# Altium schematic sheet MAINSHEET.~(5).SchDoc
size 594 x 420 mm; Scale: 1:1; Разраб.: Иванов; Обозначение документа: АБВГ.123456.001 Э3; Пров.: Петров; Утв.: Сидоров; Наименование организации: ОАО "Концерн "МПО-Гидроприбор"; Перв. применение: АБВГ.123456.000; Наименование изделия 1: Плата; Наименование изделия 2: Схема электрическая; Наименование изделия 3: принципиальная; Нач. отд.: Нач. отд.; Фамилия нач. отд.: Сидоров
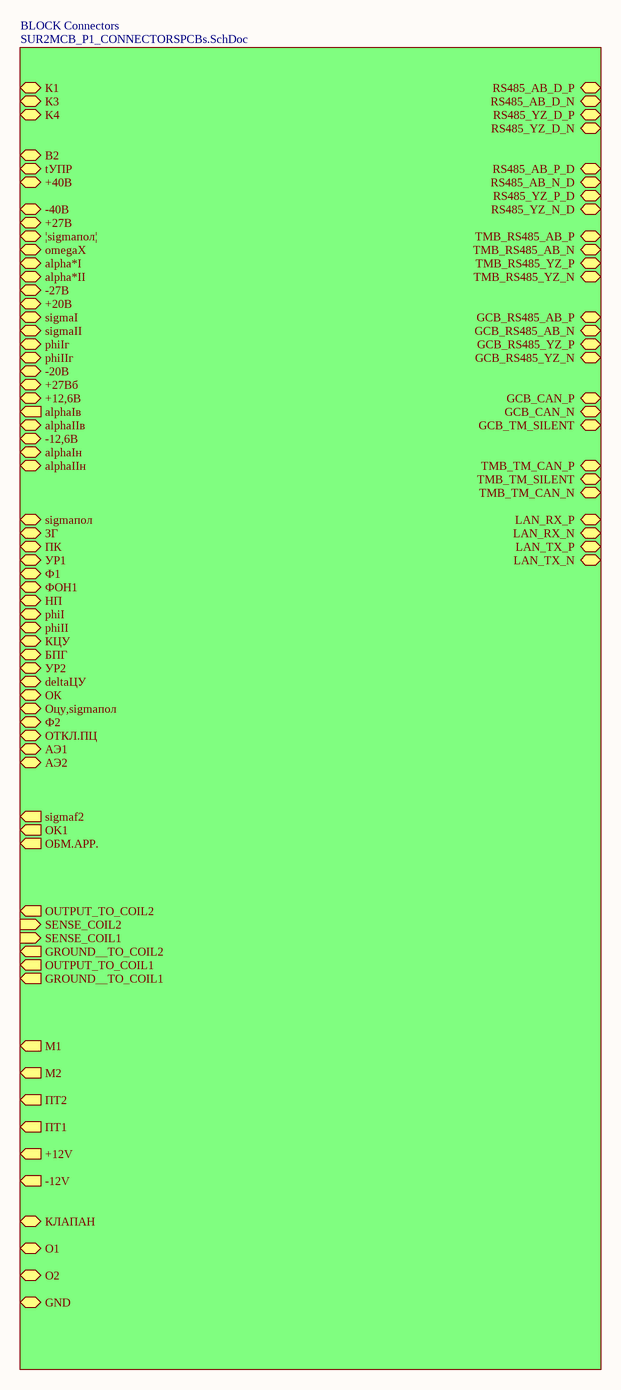
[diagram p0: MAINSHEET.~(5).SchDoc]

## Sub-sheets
BLOCK Connectors = SUR2MCB_P1_CONNECTORSPCBs.SchDoc: tУПР (bidir), B2 (bidir), K4 (bidir), +40В (bidir), К1 (bidir), К3 (bidir), OUTPUT_TO_COIL2 (out), OUTPUT_TO_COIL1 (out), GROUND__TO_COIL1 (out), SENSE_COIL2 (in), GROUND__TO_COIL2 (out), SENSE_COIL1 (in), RS485_YZ_D_N (bidir), RS485_YZ_D_P (bidir), RS485_AB_D_N (bidir), M1 (out), RS485_AB_D_P (bidir), RS485_YZ_N_D (bidir), КЛАПАН (bidir), О1 (bidir), O2 (bidir), RS485_AB_P_D (bidir), RS485_AB_N_D (bidir), RS485_YZ_P_D (bidir), TMB_RS485_AB_N (bidir), TMB_RS485_AB_P (bidir), TMB_RS485_YZ_N (bidir), TMB_RS485_YZ_P (bidir), LAN_RX_P (bidir), LAN_RX_N (bidir), LAN_TX_P (bidir), LAN_TX_N (bidir), GCB_RS485_AB_N (bidir), GCB_RS485_YZ_N (bidir), GCB_RS485_YZ_P (bidir), GCB_RS485_AB_P (bidir), GCB_CAN_P (bidir), GCB_CAN_N (bidir), GCB_TM_SILENT (bidir), TMB_TM_CAN_P (bidir), TMB_TM_SILENT (bidir), TMB_TM_CAN_N (bidir), -40В (bidir), +27В (bidir), ¦sigmaпол¦ (bidir), omegaX (bidir), alpha*II (bidir), alpha*I (bidir), -27В (bidir), +20В (bidir), -20В (bidir), sigmaII (bidir), sigmaI (bidir), phiIIг (bidir), phiIг (bidir), +27Вб (bidir), +12,6В (bidir), -12,6В (bidir), alphaIв (out), alphaIIв (bidir), alphaIIн (bidir), alphaIн (bidir), sigmaпол (bidir), ЗГ (bidir), ПК (bidir), УР1 (bidir), Ф1 (bidir), ФОН1 (bidir), НП (bidir), phiI (bidir), phiII (bidir), ПТ2 (out), +12V (out), КЦУ (bidir), БПГ (bidir), УР2 (bidir), deltaЦУ (bidir), ОК (bidir), Оцу,sigmaпол (bidir), Ф2 (bidir), ОТКЛ.ПЦ (bidir), АЭ1 (bidir), АЭ2 (bidir), ПТ1 (out), M2 (out), -12V (out), sigmaf2 (out), OK1 (out), ОБМ.АРР. (out), GND (bidir)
